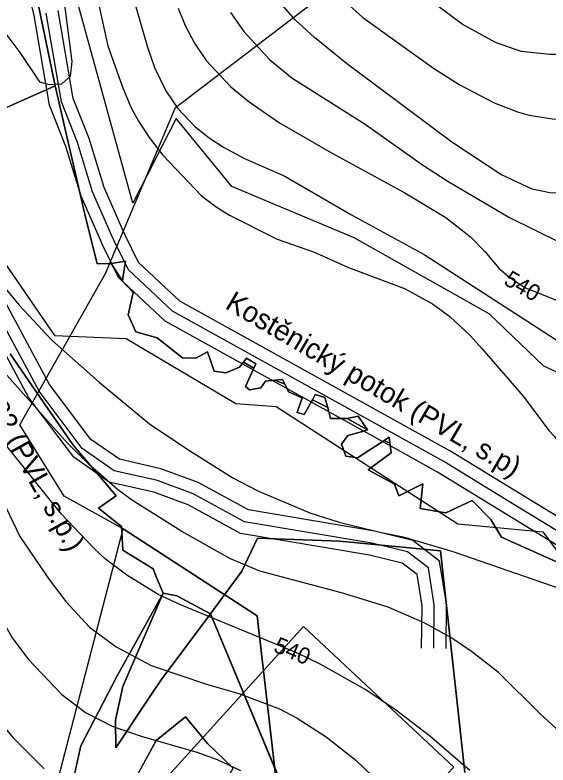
# Model space of a CAD drawing. Extents: x -709418 to -703832, y -1161719 to -1157826.
# Drawn here: x -707975.4 to -707714.4, y -1158667.8 to -1158300.7 of the extents above; entities that cross this region are included whole.
import ezdxf

# ---------------------------------------------------------------- set-up
doc = ezdxf.new("R2010")
doc.units = 0
for name, color, linetype in [('102_obvod PÚ', 7, 'Continuous'), ('103_hranice KÚ', 7, 'Continuous'), ('106_zastavitelné plochy', 7, 'Continuous'), ('120_vrstevnice hlavní', 7, 'Continuous'), ('121_vrstevnice hlavní_popis', 7, 'Continuous'), ('122_vrstevnice základní', 7, 'Continuous'), ('206_TTP_KN', 7, 'Continuous'), ('207_lesní pozemek_KN', 7, 'Continuous'), ('208_vodní plocha_KN', 7, 'Continuous'), ('501_vodní tok', 7, 'Continuous'), ('502_vodní tok_popis', 7, 'Continuous'), ('514 odvodnění - LPIS', 7, 'Continuous'), ('606_RBC_návrh', 7, 'Continuous'), ('735_OP sítí TI', 7, 'Continuous')]:
    doc.layers.add(name, color=color, linetype=linetype)

msp = doc.modelspace()

# ---------------------------------------------------------------- linework, layer by layer
at = {"layer": '102_obvod PÚ'}
msp.add_lwpolyline([(-707969.47, -1158269.23), (-707955.7, -1158335.44), (-707941.38, -1158397.48), (-707935.25, -1158422.52), (-707928.35, -1158422.26), (-707921.38, -1158421.22), (-707922.61, -1158429.42), (-707922.82, -1158430.93), (-707917.53, -1158436.46), (-707920.08, -1158447.49), (-707916.19, -1158455.69), (-707905.81, -1158458.72), (-707893.49, -1158468.51), (-707886.9, -1158468.58), (-707881.2, -1158465.52), (-707877.96, -1158475.06), (-707872.24, -1158475.81), (-707865.54, -1158473.09), (-707863.53, -1158470.54), (-707862.1, -1158468.72), (-707857.5, -1158471.45), (-707858.45, -1158473.5), (-707862.64, -1158482.56), (-707860.56, -1158484.19), (-707855.04, -1158483.15), (-707852.83, -1158479.91), (-707848.26, -1158479.43), (-707844.37, -1158479.03), (-707841.54, -1158485.08), (-707834.75, -1158488.14), (-707837.24, -1158495.25), (-707833.84, -1158496.16), (-707830.3, -1158489.91), (-707829.77, -1158488.98), (-707828.44, -1158486.37), (-707823.68, -1158487.84), (-707822.26, -1158492.81), (-707821.79, -1158494.87), (-707821.02, -1158498.21), (-707816.1, -1158498.18), (-707812.79, -1158498.16), (-707807.42, -1158497.07), (-707802.74, -1158503.8), (-707805.27, -1158504.49), (-707812.46, -1158506.45), (-707815.5, -1158510.67), (-707813.44, -1158516.55), (-707807.67, -1158517.35), (-707796.08, -1158509.85), (-707792.16, -1158507.31), (-707791.57, -1158512.52), (-707791.29, -1158514.99), (-707802.51, -1158523.33), (-707789.64, -1158530.3), (-707787.5, -1158535.99), (-707775.66, -1158530.2), (-707776.98, -1158542.16), (-707764.48, -1158544.37), (-707751.63, -1158538.23), (-707742.45, -1158547.56), (-707737.26, -1158556.26), (-707696.36, -1158574.46)], dxfattribs=at)
at = {"layer": '103_hranice KÚ'}
msp.add_lwpolyline([(-707696.36, -1158574.46), (-707737.26, -1158556.26), (-707742.45, -1158547.56), (-707751.63, -1158538.23), (-707764.48, -1158544.37), (-707776.98, -1158542.16), (-707775.66, -1158530.2), (-707787.5, -1158535.99), (-707789.64, -1158530.3), (-707802.51, -1158523.33), (-707791.29, -1158514.99), (-707791.57, -1158512.52), (-707792.16, -1158507.31), (-707796.08, -1158509.85), (-707807.67, -1158517.35), (-707813.44, -1158516.55), (-707815.5, -1158510.67), (-707812.46, -1158506.45), (-707805.27, -1158504.49), (-707802.74, -1158503.8), (-707807.42, -1158497.07), (-707812.79, -1158498.16), (-707816.1, -1158498.18), (-707821.02, -1158498.21), (-707821.79, -1158494.87), (-707822.26, -1158492.81), (-707823.68, -1158487.84), (-707828.44, -1158486.37), (-707829.77, -1158488.98), (-707830.3, -1158489.91), (-707833.84, -1158496.16), (-707837.24, -1158495.25), (-707834.75, -1158488.14), (-707841.54, -1158485.08), (-707842.65, -1158482.71), (-707844.37, -1158479.03), (-707848.26, -1158479.43), (-707852.83, -1158479.91), (-707855.04, -1158483.15), (-707860.56, -1158484.19), (-707862.64, -1158482.56), (-707858.45, -1158473.5), (-707857.5, -1158471.45), (-707862.1, -1158468.72), (-707863.53, -1158470.54), (-707865.54, -1158473.09), (-707872.24, -1158475.81), (-707877.96, -1158475.06), (-707881.21, -1158465.51), (-707886.9, -1158468.58), (-707893.49, -1158468.51), (-707905.81, -1158458.72), (-707916.19, -1158455.69), (-707920.08, -1158447.49), (-707917.53, -1158436.46), (-707922.82, -1158430.93), (-707922.61, -1158429.42), (-707921.38, -1158421.22), (-707928.35, -1158422.26), (-707935.25, -1158422.52), (-707941.38, -1158397.48), (-707955.7, -1158335.44), (-707969.47, -1158269.23)], dxfattribs=at)
at = {"layer": '106_zastavitelné plochy'}
msp.add_lwpolyline([(-707834.22, -1158600.04), (-707760.59, -1158668.87), (-707812.4, -1158723.38), (-707830.81, -1158705.67), (-707847.17, -1158723.38), (-707900.34, -1158672.96), (-707834.22, -1158600.04)], dxfattribs=at)
at = {"layer": '120_vrstevnice hlavní'}
for points in [[(-707752.74, -1158670.43), (-707772.46, -1158653.57), (-707789.03, -1158640.71), (-707803.6, -1158631), (-707825.6, -1158618.57), (-707837.03, -1158613), (-707893.61, -1158589.71), (-707905.32, -1158584.28), (-707920.61, -1158574.85), (-707931.04, -1158566.99), (-707936.61, -1158561.85), (-707952.61, -1158544.99), (-707994.9, -1158492.71), (-708006.18, -1158477.28), (-708027.61, -1158446.42), (-708039.9, -1158430.99), (-708053.61, -1158414.99), (-708072.04, -1158396.13), (-708082.9, -1158383.56), (-708111.33, -1158345.56), (-708133.62, -1158318.41), (-708155.62, -1158295.7)], [(-707895.46, -1158297.27), (-707892.03, -1158305.84), (-707887.46, -1158314.41), (-707881.75, -1158322.98), (-707869.75, -1158335.84), (-707860.75, -1158343.13), (-707845.89, -1158353.41), (-707820.46, -1158368.13), (-707784.46, -1158387.7), (-707764.46, -1158399.84)], [(-707764.46, -1158399.84), (-707752.46, -1158409.27), (-707745.31, -1158416.42), (-707738.46, -1158424.56), (-707733.6, -1158428.84), (-707725.74, -1158433.99), (-707694.45, -1158446.56), (-707686.45, -1158447.7), (-707657.31, -1158448.42), (-707648.31, -1158449.7), (-707628.7, -1158454.43), (-707609.02, -1158462.28), (-707599.59, -1158466.28), (-707577.16, -1158480.7), (-707552.59, -1158499.56)]]:
    msp.add_lwpolyline(points, dxfattribs=at)
at = {"layer": '122_vrstevnice základní'}
for points in [[(-707564.45, -1158400.41), (-707588.73, -1158391.7), (-707620.16, -1158383.13), (-707637.02, -1158380.99), (-707652.45, -1158380.56), (-707666.17, -1158381.41), (-707691.31, -1158386.84), (-707700.45, -1158387.99), (-707713.6, -1158387.7), (-707722.17, -1158385.99), (-707737.6, -1158378.84), (-707761.6, -1158362.98), (-707813.03, -1158324.41), (-707828.74, -1158311.7), (-707838.17, -1158303.12), (-707843.75, -1158296.7), (-707847.6, -1158290.7), (-707851.6, -1158282.7), (-707857.18, -1158268.69), (-707860.75, -1158252.69), (-707863.46, -1158220.69)], [(-707553.3, -1158344.98), (-707579.59, -1158332.55), (-707593.59, -1158327.27), (-707615.59, -1158320.98), (-707629.59, -1158318.27), (-707639.59, -1158317.27), (-707657.59, -1158316.98), (-707699.6, -1158319.98), (-707713.6, -1158319.98), (-707727.6, -1158318.55), (-707740.17, -1158314.12), (-707756.46, -1158305.12), (-707776.17, -1158290.27), (-707798.6, -1158269.69), (-707807.6, -1158259.98), (-707813.17, -1158252.41), (-707819.32, -1158238.69)], [(-708005.61, -1158282.55), (-707995.61, -1158291.84), (-707983.47, -1158305.27), (-707973.04, -1158318.98), (-707963.47, -1158333.41), (-707958.73, -1158334.76), (-707952.45, -1158334.34), (-707948.25, -1158330.56), (-707947.42, -1158323.44), (-707951.19, -1158294.51), (-707959.35, -1158250.85)], [(-707943.18, -1158255.84), (-707930.04, -1158315.84), (-707923.04, -1158335.55), (-707918.75, -1158345.84), (-707915.04, -1158352.7), (-707909.75, -1158360.7), (-707903.03, -1158369.27), (-707884.03, -1158389.27), (-707876.46, -1158394.99), (-707870.32, -1158398.7), (-707847.03, -1158410.42), (-707829.32, -1158416.56), (-707812.17, -1158424.27), (-707784.74, -1158434.56), (-707771.03, -1158441.99), (-707762.46, -1158448.27), (-707752.31, -1158457.7), (-707746.88, -1158463.85)], [(-707916.89, -1158294.41), (-707910.61, -1158316.41), (-707907.18, -1158326.41), (-707901.6, -1158337.84), (-707895.75, -1158346.41), (-707887.46, -1158355.13), (-707880.32, -1158360.84), (-707873.32, -1158365.41), (-707863.32, -1158370.7), (-707843.32, -1158379.56), (-707811.03, -1158398.27), (-707775.03, -1158417.99), (-707695.74, -1158469.13), (-707686.74, -1158473.56), (-707678.17, -1158477.28), (-707650.74, -1158485.56), (-707633.59, -1158491.99)], [(-707813.17, -1158294.7), (-707805.03, -1158301.84), (-707770.46, -1158326.7), (-707757.89, -1158334.7), (-707740.74, -1158343.7), (-707729.31, -1158348.13), (-707723.6, -1158349.7), (-707712.17, -1158351.56), (-707700.74, -1158352.13), (-707683.88, -1158349.7)], [(-708079.9, -1158297.84), (-708067.47, -1158319.84), (-708048.76, -1158348.13), (-708039.33, -1158360.7), (-708015.04, -1158388.99), (-707992.04, -1158420.42), (-707973.47, -1158442.7), (-707957.32, -1158459.85), (-707934.18, -1158480.42), (-707909.61, -1158500.71), (-707890.75, -1158513.42), (-707868.75, -1158527.14)], [(-707869.89, -1158299.55), (-707863.32, -1158308.7), (-707850.75, -1158322.41), (-707839.89, -1158331.41), (-707803.89, -1158354.13), (-707775.89, -1158373.98), (-707763.89, -1158381.84), (-707733.6, -1158399.7)], [(-708253.34, -1158318.27), (-708237.05, -1158321.84), (-708225.91, -1158325.41), (-708210.48, -1158331.98), (-708193.33, -1158340.84), (-708186.48, -1158344.98), (-708173.62, -1158354.7), (-708162.05, -1158365.41), (-708137.47, -1158390.13), (-708128.47, -1158400.13), (-708114.62, -1158417.42), (-708086.61, -1158455.56), (-708071.9, -1158474.13), (-708067.19, -1158481.28), (-708045.47, -1158520.99), (-708035.04, -1158541.56), (-708029.33, -1158554.99), (-708020.47, -1158582.14), (-708012.75, -1158602.14), (-708005.61, -1158615.28), (-707992.61, -1158634.43), (-707986.04, -1158643.14), (-707976.18, -1158654.71), (-707961.18, -1158669.57)], [(-708165.05, -1158343.41), (-708142.19, -1158363.84), (-708133.62, -1158373.27), (-708111.19, -1158401.56), (-708062.47, -1158455.56), (-708044.61, -1158479.56), (-708035.47, -1158493.56), (-708019.18, -1158521.56), (-708009.9, -1158539.56), (-708003.75, -1158553.56), (-707984.9, -1158591.57), (-707976.75, -1158605.57), (-707968.89, -1158616.14), (-707952.47, -1158633.28), (-707940.89, -1158642.14), (-707927.89, -1158648.71), (-707913.61, -1158653.71), (-707886.46, -1158661.43), (-707876.46, -1158665.14), (-707865.03, -1158670.43)], [(-707733.6, -1158399.7), (-707708.45, -1158411.99), (-707698.45, -1158415.84), (-707692.45, -1158416.99), (-707673.02, -1158415.27), (-707663.88, -1158415.7), (-707633.31, -1158418.84), (-707609.31, -1158423.7), (-707589.31, -1158429.42), (-707579.31, -1158433.13), (-707561.3, -1158441.42)], [(-707679.02, -1158683), (-707692.31, -1158667.29), (-707701.6, -1158657.86), (-707718.17, -1158642.85), (-707738.74, -1158622.43), (-707751.88, -1158612.14), (-707762.03, -1158605.42), (-707774.74, -1158598.28), (-707792.74, -1158590.57), (-707815.6, -1158583.57), (-707855.6, -1158572.85), (-707869.89, -1158566.85), (-707893.75, -1158553.56), (-707918.46, -1158537.99), (-707925.18, -1158532.85), (-707938.47, -1158521.28), (-707949.89, -1158510.13), (-707993.18, -1158461.85)], [(-707746.88, -1158463.85), (-707726.6, -1158487.28), (-707714.03, -1158504.13), (-707711.31, -1158506.99), (-707703.74, -1158518.42), (-707696.31, -1158527.14), (-707683.02, -1158539.56), (-707646.8, -1158568.99), (-707641.17, -1158575.99)], [(-707868.75, -1158527.14), (-707856.18, -1158533.71), (-707831.03, -1158544.42), (-707816.74, -1158548.85), (-707796.74, -1158553.85), (-707785.32, -1158556.14), (-707761.05, -1158563.32), (-707699.13, -1158584.7), (-707675.14, -1158593.86), (-707655.96, -1158598.22), (-707648.54, -1158596.47), (-707643.74, -1158590.37), (-707640.69, -1158582.95), (-707641.17, -1158575.99)], [(-707985.47, -1158530.28), (-707973.04, -1158555.85), (-707958.75, -1158577), (-707950.47, -1158587.71), (-707938.89, -1158600.28), (-707925.89, -1158610), (-707908.75, -1158619.14), (-707881.6, -1158628.28), (-707865.89, -1158632.71), (-707845.89, -1158640.28), (-707837.32, -1158644.85), (-707823.03, -1158654), (-707808.46, -1158665.43), (-707780.46, -1158692.29)]]:
    msp.add_lwpolyline(points, dxfattribs=at)
at = {"layer": '206_TTP_KN'}
for p, q in [((-707969.47, -1158269.23), (-707955.7, -1158335.44)), ((-707955.7, -1158335.44), (-708029.7, -1158368.19)), ((-708029.7, -1158368.19), (-707955.7, -1158335.44)), ((-707955.7, -1158335.44), (-707941.38, -1158397.48)), ((-707941.38, -1158397.48), (-707935.25, -1158422.52)), ((-707935.25, -1158422.52), (-707928.35, -1158422.26)), ((-707928.35, -1158422.26), (-707922.82, -1158430.93)), ((-707922.82, -1158430.93), (-707917.53, -1158436.46)), ((-707917.53, -1158436.46), (-707920.08, -1158447.49)), ((-707920.08, -1158447.49), (-707916.19, -1158455.69)), ((-707916.19, -1158455.69), (-707905.81, -1158458.72)), ((-707905.81, -1158458.72), (-707893.49, -1158468.51)), ((-707959.49, -1158493.09), (-707977.75, -1158466.52)), ((-707977.75, -1158466.52), (-707959.49, -1158493.09)), ((-707893.49, -1158468.51), (-707886.9, -1158468.58)), ((-707886.9, -1158468.58), (-707881.2, -1158465.52)), ((-707881.2, -1158465.52), (-707877.96, -1158475.06)), ((-707865.54, -1158473.09), (-707863.53, -1158470.54)), ((-707863.53, -1158470.54), (-707858.45, -1158473.5)), ((-707877.96, -1158475.06), (-707872.24, -1158475.81)), ((-707872.24, -1158475.81), (-707865.54, -1158473.09)), ((-707858.45, -1158473.5), (-707862.64, -1158482.56)), ((-707855.04, -1158483.15), (-707852.83, -1158479.91)), ((-707852.83, -1158479.91), (-707848.26, -1158479.43)), ((-707848.26, -1158479.43), (-707843.28, -1158481.37)), ((-707862.64, -1158482.56), (-707860.56, -1158484.19)), ((-707860.56, -1158484.19), (-707855.04, -1158483.15)), ((-707843.28, -1158481.37), (-707841.54, -1158485.08)), ((-707841.54, -1158485.08), (-707834.75, -1158488.14)), ((-707834.75, -1158488.14), (-707837.24, -1158495.25)), ((-707833.84, -1158496.16), (-707830.3, -1158489.91)), ((-707830.3, -1158489.91), (-707829.77, -1158488.98)), ((-707829.77, -1158488.98), (-707822.26, -1158492.81)), ((-707946.71, -1158511.46), (-707959.49, -1158493.09)), ((-707959.49, -1158493.09), (-707946.71, -1158511.46)), ((-707822.26, -1158492.81), (-707821.79, -1158494.87)), ((-707821.79, -1158494.87), (-707821.02, -1158498.21)), ((-707837.24, -1158495.25), (-707833.84, -1158496.16)), ((-707821.02, -1158498.21), (-707816.1, -1158498.18)), ((-707816.1, -1158498.18), (-707812.79, -1158498.16)), ((-707812.79, -1158498.16), (-707802.74, -1158503.8)), ((-707805.27, -1158504.49), (-707812.46, -1158506.45)), ((-707802.74, -1158503.8), (-707805.27, -1158504.49)), ((-707812.46, -1158506.45), (-707815.5, -1158510.67)), ((-707796.08, -1158509.85), (-707794.66, -1158508.93)), ((-707794.66, -1158508.93), (-707791.82, -1158510.28)), ((-707925.92, -1158535.98), (-707946.71, -1158511.46)), ((-707946.71, -1158511.46), (-707925.92, -1158535.98)), ((-707815.5, -1158510.67), (-707813.44, -1158516.55)), ((-707807.67, -1158517.35), (-707796.08, -1158509.85)), ((-707791.82, -1158510.28), (-707791.57, -1158512.52)), ((-707791.57, -1158512.52), (-707791.29, -1158514.99)), ((-707813.44, -1158516.55), (-707807.67, -1158517.35)), ((-707791.29, -1158514.99), (-707802.51, -1158523.33)), ((-707802.51, -1158523.33), (-707789.64, -1158530.3)), ((-707789.64, -1158530.3), (-707787.5, -1158535.99)), ((-707787.5, -1158535.99), (-707775.66, -1158530.2)), ((-707775.66, -1158530.2), (-707776.98, -1158542.16)), ((-707934.5, -1158542), (-707925.92, -1158535.98)), ((-707925.92, -1158535.98), (-707934.5, -1158542)), ((-707764.48, -1158544.37), (-707751.63, -1158538.23)), ((-707751.63, -1158538.23), (-707742.45, -1158547.56)), ((-707923.21, -1158551.11), (-707934.5, -1158542)), ((-707934.5, -1158542), (-707923.21, -1158551.11)), ((-707776.98, -1158542.16), (-707764.48, -1158544.37)), ((-707742.45, -1158547.56), (-707737.26, -1158556.26)), ((-707922.57, -1158562.56), (-707923.21, -1158551.11)), ((-707923.21, -1158551.11), (-707922.57, -1158562.56)), ((-707856.73, -1158556.81), (-707864.4, -1158572.9)), ((-707864.4, -1158572.9), (-707856.73, -1158556.81)), ((-707816.41, -1158558.2), (-707856.73, -1158556.81)), ((-707856.73, -1158556.81), (-707816.41, -1158558.2)), ((-707737.26, -1158556.26), (-707696.36, -1158574.46)), ((-707767.14, -1158562.91), (-707816.41, -1158558.2)), ((-707816.41, -1158558.2), (-707767.14, -1158562.91)), ((-707907.76, -1158571.75), (-707922.57, -1158562.56)), ((-707922.57, -1158562.56), (-707907.76, -1158571.75)), ((-707755.13, -1158671.44), (-707767.14, -1158562.91)), ((-707767.14, -1158562.91), (-707755.13, -1158671.44)), ((-707906.15, -1158575.96), (-707907.76, -1158571.75)), ((-707907.76, -1158571.75), (-707906.15, -1158575.96)), ((-707864.4, -1158572.9), (-707879.71, -1158593.85)), ((-707879.71, -1158593.85), (-707864.4, -1158572.9)), ((-707902.91, -1158583.6), (-707906.15, -1158575.96)), ((-707906.15, -1158575.96), (-707902.91, -1158583.6)), ((-707902.91, -1158583.6), (-707925.4, -1158624.2)), ((-707896.22, -1158585.01), (-707902.91, -1158583.6)), ((-707879.71, -1158593.85), (-707896.22, -1158585.01)), ((-707833.2, -1158705.12), (-707879.71, -1158593.85)), ((-707925.4, -1158624.2), (-707943.22, -1158658.45)), ((-707906.37, -1158655.83), (-707891.88, -1158644.27)), ((-707891.88, -1158644.27), (-707881.25, -1158657.18)), ((-707921.35, -1158683.16), (-707906.37, -1158655.83)), ((-707943.22, -1158658.45), (-707954.54, -1158709.31)), ((-707881.25, -1158657.18), (-707868.54, -1158669.24))]:
    msp.add_line(p, q, dxfattribs=at)
for points in [[(-707961.41, -1158800.42), (-707959.9, -1158734), (-707954.54, -1158709.31), (-707943.22, -1158658.45), (-707925.4, -1158624.2), (-707902.91, -1158583.6), (-707922.57, -1158629.27), (-707926.16, -1158645.83), (-707926.04, -1158659.36), (-707909.53, -1158634.57), (-707903.85, -1158626.09), (-707879.71, -1158593.85), (-707833.2, -1158705.12), (-707848.43, -1158723.45), (-707874.98, -1158741.29), (-707879.6, -1158745.09), (-707899.27, -1158752.13), (-707914.98, -1158744.96), (-707914.49, -1158772.3), (-707908.5, -1158781.68), (-707914.57, -1158787.64), (-707942, -1158791.53), (-707961.41, -1158800.42)], [(-707946.33, -1158712.56), (-707913.29, -1158720.62), (-707897.87, -1158721.9), (-707868.54, -1158669.24), (-707881.25, -1158657.18), (-707891.88, -1158644.27), (-707906.37, -1158655.83), (-707921.35, -1158683.16), (-707939.55, -1158686.15), (-707943.97, -1158698.5), (-707946.33, -1158712.56)]]:
    msp.add_lwpolyline(points, dxfattribs=at)
at = {"layer": '207_lesní pozemek_KN'}
for p, q in [((-707922.57, -1158629.27), (-707902.91, -1158583.6)), ((-707902.91, -1158583.6), (-707896.22, -1158585.01)), ((-707896.22, -1158585.01), (-707879.71, -1158593.85)), ((-707879.71, -1158593.85), (-707903.85, -1158626.09)), ((-707903.85, -1158626.09), (-707909.53, -1158634.57)), ((-707926.16, -1158645.83), (-707922.57, -1158629.27)), ((-707909.53, -1158634.57), (-707926.04, -1158659.36)), ((-707926.04, -1158659.36), (-707926.16, -1158645.83))]:
    msp.add_line(p, q, dxfattribs=at)
at = {"layer": '208_vodní plocha_KN'}
for p, q in [((-707928.35, -1158422.26), (-707921.38, -1158421.22)), ((-707921.38, -1158421.22), (-707922.61, -1158429.42)), ((-707922.82, -1158430.93), (-707928.35, -1158422.26)), ((-707922.61, -1158429.42), (-707922.82, -1158430.93)), ((-707863.53, -1158470.54), (-707862.1, -1158468.72)), ((-707862.1, -1158468.72), (-707857.5, -1158471.45)), ((-707858.45, -1158473.5), (-707863.53, -1158470.54)), ((-707857.5, -1158471.45), (-707858.45, -1158473.5)), ((-707848.26, -1158479.43), (-707844.37, -1158479.03)), ((-707843.28, -1158481.37), (-707848.26, -1158479.43)), ((-707844.37, -1158479.03), (-707843.28, -1158481.37)), ((-707829.77, -1158488.98), (-707828.44, -1158486.37)), ((-707828.44, -1158486.37), (-707823.68, -1158487.84)), ((-707822.26, -1158492.81), (-707829.77, -1158488.98)), ((-707823.68, -1158487.84), (-707822.26, -1158492.81)), ((-707812.79, -1158498.16), (-707807.42, -1158497.07)), ((-707802.74, -1158503.8), (-707812.79, -1158498.16)), ((-707807.42, -1158497.07), (-707802.74, -1158503.8)), ((-707794.66, -1158508.93), (-707792.16, -1158507.31)), ((-707791.82, -1158510.28), (-707794.66, -1158508.93)), ((-707792.16, -1158507.31), (-707791.82, -1158510.28))]:
    msp.add_line(p, q, dxfattribs=at)
at = {"layer": '501_vodní tok'}
for points in [[(-707770.36, -1158610.66), (-707770.12, -1158589.37), (-707773.03, -1158571.25), (-707783.24, -1158563.39), (-707800.68, -1158559.16), (-707863.04, -1158548.7), (-707888.19, -1158535.02), (-707905.68, -1158528.53), (-707926.81, -1158523.75), (-707942.48, -1158512.81), (-707963.62, -1158484.78), (-708001.16, -1158415.06), (-708017.55, -1158383.96), (-708028.85, -1158366.87), (-708064.52, -1158292.54)], [(-707770.36, -1158610.66), (-707770.12, -1158589.37), (-707773.03, -1158571.25), (-707783.24, -1158563.39), (-707800.68, -1158559.16), (-707863.04, -1158548.7), (-707888.19, -1158535.02), (-707905.68, -1158528.53), (-707926.81, -1158523.75), (-707942.48, -1158512.81), (-707963.62, -1158484.78), (-708001.16, -1158415.06), (-708017.55, -1158383.96), (-708028.85, -1158366.87), (-708064.52, -1158292.54)], [(-707552.66, -1158642.03), (-707570.15, -1158633.83), (-707601.12, -1158617.43), (-707623.72, -1158603.76), (-707643.39, -1158593.84), (-707731.22, -1158540.19), (-707765.45, -1158519.26), (-707785.24, -1158508.3), (-707898.35, -1158445.64), (-707919.84, -1158425.46), (-707927, -1158410.94), (-707927.96, -1158408.78), (-707937.41, -1158387.2), (-707944.81, -1158363.13), (-707952.7, -1158343.23), (-707960.11, -1158299.73)]]:
    msp.add_lwpolyline(points, dxfattribs=at)
at = {"layer": '514 odvodnění - LPIS'}
msp.add_lwpolyline([(-707489.16, -1159005.71), (-707569.43, -1159066.92), (-707603.01, -1158988.93), (-707648.79, -1158918.72), (-707754.07, -1158757.73), (-707821.22, -1158857.62), (-707930.88, -1158835.7), (-707845.96, -1158689.5), (-707856.8, -1158594.73), (-707922.5, -1158552.13), (-707951.37, -1158536.17), (-707973.13, -1158501.33), (-707931.06, -1158427.16), (-707896.86, -1158345.91), (-707805.32, -1158276.05), (-707728.07, -1158192.72), (-707668.81, -1158046.81), (-707588.53, -1158111.37), (-707569.75, -1158097.71), (-707553.1, -1158117.35), (-707594.94, -1158189.49), (-707609.56, -1158341.44), (-707552.38, -1158375.86)], dxfattribs=at)
msp.add_lwpolyline([(-707648.79, -1158918.72), (-707692.14, -1159014.51), (-707682.75, -1159045.59), (-707665.73, -1159092.42), (-707668.38, -1159119.25), (-707742.37, -1159079.52), (-707741.89, -1159047.31), (-707785.4, -1159018.6), (-707877.26, -1158898.12), (-707934.28, -1158855.79), (-707969.39, -1158831.92), (-707961.99, -1158704.22), (-707922.5, -1158552.13), (-707856.8, -1158594.73), (-707845.96, -1158689.5), (-707930.88, -1158835.7), (-707821.22, -1158857.62), (-707754.07, -1158757.73)], close=True, dxfattribs=at)
at = {"layer": '606_RBC_návrh'}
for points in [[(-708621.34, -1158919.97), (-708569.6, -1158864.8), (-708533.12, -1158802.69), (-708467.27, -1158745.84), (-708382.3, -1158679.26), (-708317.54, -1158662.95), (-708278.48, -1158513.72), (-708252.68, -1158400.3), (-708216.1, -1158388.94), (-708192.86, -1158365.22), (-708087.56, -1158238.22), (-707982.26, -1158419.57), (-707956.06, -1158457.62), (-707920.96, -1158459.1), (-707867.27, -1158490.87), (-707847.49, -1158492.35), (-707758.51, -1158549.67), (-707716.98, -1158553.62), (-707663.59, -1158625.77), (-707619.1, -1158657.4), (-707563.23, -1158667.28)], [(-707545.43, -1158532.37), (-707617.61, -1158518.04), (-707716.49, -1158472.58), (-707743.18, -1158446.89), (-707809.43, -1158409.83), (-707869.25, -1158384.62), (-707896.54, -1158351.28), (-707917.8, -1158392.79), (-707958.34, -1158245.04)]]:
    msp.add_lwpolyline(points, dxfattribs=at)
at = {"layer": '735_OP sítí TI'}
for points in [[(-707555.22, -1158647.46), (-707572.83, -1158639.2), (-707604.08, -1158622.65), (-707626.62, -1158609.01), (-707646.31, -1158599.09), (-707734.35, -1158545.31), (-707768.47, -1158524.45), (-707788.15, -1158513.54), (-707901.91, -1158450.52), (-707924.74, -1158429.09), (-707932.43, -1158413.49), (-707933.45, -1158411.21), (-707943.04, -1158389.29), (-707950.47, -1158365.12), (-707958.51, -1158344.86), (-707965.99, -1158300.93), (-707971.69, -1158277.33)], [(-707764.36, -1158610.73), (-707764.11, -1158588.92), (-707767.49, -1158567.95), (-707780.58, -1158557.86), (-707799.47, -1158553.28), (-707861.06, -1158542.94), (-707885.7, -1158529.55), (-707903.96, -1158522.77), (-707924.34, -1158518.15), (-707938.27, -1158508.44), (-707958.55, -1158481.54), (-707995.86, -1158412.24), (-708012.38, -1158380.9), (-708023.62, -1158363.91), (-708059.16, -1158289.85)], [(-707776.36, -1158610.59), (-707776.12, -1158589.81), (-707778.58, -1158574.55), (-707785.89, -1158568.92), (-707801.88, -1158565.04), (-707865.02, -1158554.45), (-707890.68, -1158540.5), (-707907.39, -1158534.29), (-707929.28, -1158529.34), (-707946.7, -1158517.18), (-707968.69, -1158488.03), (-708006.45, -1158417.88), (-708022.72, -1158387.02), (-708034.08, -1158369.84), (-708069.89, -1158295.23)], [(-707550.09, -1158636.61), (-707567.47, -1158628.46), (-707598.16, -1158612.21), (-707620.81, -1158598.5), (-707640.48, -1158588.6), (-707728.09, -1158535.07), (-707762.43, -1158514.07), (-707782.33, -1158503.05), (-707894.79, -1158440.75), (-707914.94, -1158421.83), (-707921.57, -1158408.39), (-707922.47, -1158406.36), (-707931.77, -1158385.11), (-707939.14, -1158361.14), (-707946.89, -1158341.6), (-707954.23, -1158298.52)]]:
    msp.add_lwpolyline(points, dxfattribs=at)

# ---------------------------------------------------------------- texts
at = {"layer": '121_vrstevnice hlavní_popis'}
for rotation, p in [(329.4682, (-707736.6, -1158432.2)), (337.4424, (-707849.33, -1158612.15))]:
    msp.add_text('540', height=8, rotation=rotation, dxfattribs=at).set_placement(p)
at = {"layer": '502_vodní tok_popis'}
for s, rotation, p in [('IDVT 10259782 (PVL, s.p.)', 299.004, (-708027.24, -1158423.76)), ('Kostěnický potok (PVL, s.p)', 329.5705, (-707873.06, -1158444.01))]:
    msp.add_text(s, height=10, rotation=rotation, dxfattribs=at).set_placement(p)

doc.saveas('drawing.dxf')
